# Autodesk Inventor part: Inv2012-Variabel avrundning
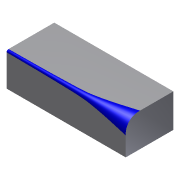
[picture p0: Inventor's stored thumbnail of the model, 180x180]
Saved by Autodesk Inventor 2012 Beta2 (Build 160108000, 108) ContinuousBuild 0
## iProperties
Created: 2011-02
Part Number: Inv2012-Variabel avrundning
Material: Default
Document SubType Name: Modeling
Designer: ehttln
Density: 1 g/cm^3
Author: ehttln
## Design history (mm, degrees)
sketch "Sketch1"
  geometry: L1 (-12.635, -13.802)-(112.365, -13.802); L2 (112.365, -13.802)-(112.365, 36.198); L3 (112.365, 36.198)-(-12.635, 36.198); L4 (-12.635, 36.198)-(-12.635, -13.802); 1 further point
  constraints: 8 end point, 2 parallel, 1 horizontal, 1 perpendicular
  dimensions: "d0" = 50 distance of L3.end L1.start; "d1" = 125 distance of L1.start L1.end
extrude "Extrusion1" new body sketch "Sketch1" distance "d2" = 35; taper "d3" = 0 deg
fillet "Fillet1" dims "d4" = 15, "d5" = 2, "d6" = 3, "d7" = 5, "d8" = 5, "d9" = 3
body "Solid1"
